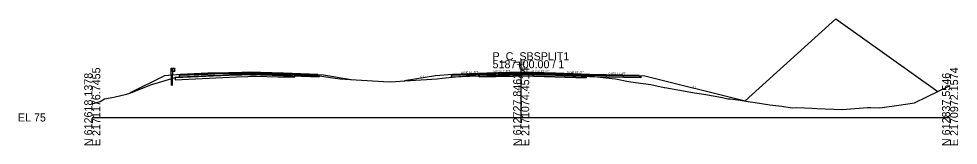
# Model space of a CAD drawing. Extents: x -26 to 1303, y -3010 to 12033.
# Drawn here: x -25.7 to 302.8, y 7990.3 to 8034.5 of the extents above; entities that cross this region are included whole.
import ezdxf

# ---------------------------------------------------------------- set-up
doc = ezdxf.new("R2010")
doc.units = 0
for name, color, linetype in [('RD_GPK_XS_Cell', 7, 'Continuous'), ('RD_PD_Final_TrvlWay', 7, 'Continuous'), ('RD_Sketch10', 7, 'Continuous'), ('RD_XS_Base', 7, 'Continuous'), ('RD_XS_ExGround', 7, 'Continuous'), ('RD_XS_ExPaveRet', 7, 'Continuous'), ('RD_XS_GR', 7, 'Continuous'), ('RD_XS_Greenside', 7, 'Continuous'), ('RD_XS_Pave', 7, 'Continuous'), ('RD_XS_PaveOvlay_CP', 7, 'Continuous'), ('RD_XS_TieSlope', 7, 'Continuous'), ('RD_XS_TX_Elev_EX', 7, 'Continuous'), ('RD_XS_TX_Elev_PR', 7, 'Continuous'), ('RD_XS_TX_Slope', 7, 'Continuous')]:
    doc.layers.add(name, color=color, linetype=linetype)

msp = doc.modelspace()

# ---------------------------------------------------------------- linework, layer by layer
at = {"layer": 'RD_GPK_XS_Cell'}
for p, q in [((150, 8000), (150, 8020)), ((0, 8000), (150, 8000)), ((150, 8000), (300, 8000))]:
    msp.add_line(p, q, dxfattribs=at)
at = {"layer": 'RD_PD_Final_TrvlWay'}
msp.add_lwpolyline([(28.05, 8011.23), (28.05, 8014.83), (27.55, 8014.79), (27.55, 8011.23)], dxfattribs=at)
at = {"layer": 'RD_Sketch10'}
msp.add_lwpolyline([(228.37, 8005.78), (260.08, 8034.49), (295.68, 8009.06)], dxfattribs=at)
at = {"layer": 'RD_XS_Base'}
for p, q in [((30.78, 8014.74), (30.38, 8014.72)), ((30.38, 8014.72), (30.38, 8014.62)), ((30.38, 8014.62), (30.38, 8014.22)), ((30.38, 8014.22), (30.78, 8014.24)), ((30.88, 8014.74), (30.78, 8014.74)), ((30.78, 8014.24), (30.88, 8014.24)), ((40.4, 8015.12), (30.88, 8014.74)), ((30.88, 8014.24), (40.4, 8014.62)), ((42.88, 8015.22), (40.4, 8015.12)), ((40.4, 8014.62), (42.88, 8014.72)), ((52.33, 8015.41), (42.88, 8015.22)), ((42.88, 8014.72), (52.33, 8014.91)), ((54.88, 8015.46), (52.33, 8015.41)), ((52.33, 8014.91), (54.88, 8014.96)), ((54.88, 8015.59), (54.88, 8015.62)), ((54.88, 8015.62), (54.88, 8015.48)), ((54.88, 8015.46), (54.88, 8015.62)), ((54.88, 8015.62), (54.88, 8015.62)), ((54.88, 8015.62), (54.88, 8015.62)), ((54.88, 8015.62), (54.88, 8014.96)), ((54.88, 8015.46), (54.88, 8015.59)), ((54.88, 8015.48), (54.88, 8014.96)), ((54.88, 8015.36), (54.88, 8015.46)), ((54.88, 8014.96), (54.88, 8015.46)), ((54.88, 8015.46), (54.88, 8015.46)), ((54.88, 8015.46), (54.88, 8015.46)), ((54.88, 8015.46), (54.88, 8015.46)), ((66.88, 8015.22), (54.88, 8015.46)), ((54.88, 8014.96), (54.88, 8015.36)), ((54.88, 8014.96), (54.88, 8014.96)), ((54.88, 8014.96), (54.88, 8014.96)), ((54.88, 8014.96), (66.88, 8014.72)), ((78.88, 8014.74), (66.88, 8015.22)), ((66.88, 8014.72), (79.38, 8014.22)), ((68.88, 8015.14), (68.88, 8015.14)), ((68.88, 8014.64), (68.88, 8014.64)), ((79.38, 8014.72), (78.88, 8014.74)), ((78.88, 8014.74), (78.88, 8014.74)), ((79.38, 8014.22), (79.38, 8014.72)), ((79.38, 8014.72), (79.38, 8014.72)), ((126, 8014.74), (125.5, 8014.72)), ((125.5, 8014.72), (125.5, 8014.72)), ((125.5, 8014.72), (125.5, 8014.22)), ((125.5, 8014.22), (126, 8014.24)), ((138, 8015.22), (126, 8014.74)), ((126, 8014.74), (126, 8014.74)), ((126, 8014.24), (138, 8014.72)), ((126, 8014.24), (126, 8014.24)), ((136, 8015.14), (136, 8015.14)), ((136, 8014.64), (136, 8014.64)), ((150, 8015.46), (138, 8015.22)), ((138, 8014.72), (150, 8014.96)), ((150, 8014.96), (150, 8015.62)), ((150, 8015.62), (150, 8015.62)), ((150, 8015.62), (150, 8015.62)), ((150, 8015.62), (150, 8015.46)), ((150, 8015.46), (150, 8015.46)), ((150, 8015.46), (162, 8015.22)), ((150, 8015.46), (150, 8015.46)), ((150, 8014.96), (150, 8015.46)), ((150, 8015.46), (150, 8015.46)), ((150, 8015.46), (150, 8015.46)), ((162, 8014.72), (150, 8014.96)), ((150, 8014.96), (150, 8014.96)), ((150, 8014.96), (150, 8014.96)), ((162, 8015.22), (162, 8015.22)), ((162, 8015.22), (174, 8014.74)), ((174, 8014.24), (162, 8014.72)), ((162, 8014.72), (162, 8014.72)), ((174, 8014.74), (174, 8014.74)), ((174, 8014.74), (191.3, 8014.39)), ((191.8, 8013.88), (174, 8014.24)), ((174, 8014.24), (174, 8014.24)), ((191.3, 8014.39), (191.3, 8014.39)), ((191.3, 8014.39), (191.8, 8014.38)), ((191.8, 8014.38), (191.8, 8014.38)), ((191.8, 8014.38), (191.8, 8013.88))]:
    msp.add_line(p, q, dxfattribs=at)
at = {"layer": 'RD_XS_ExGround'}
msp.add_lwpolyline([(0, 8004.82), (2.39, 8005.42), (2.74, 8005.56), (4.29, 8006.5), (7.59, 8007.12), (11.93, 8008.2), (13.11, 8008.48), (13.51, 8008.57), (14.62, 8009.07), (20.67, 8011.5), (21.98, 8011.83), (28.94, 8013.93), (50.49, 8014.93), (55.37, 8015.16), (57.3, 8015.13), (70.85, 8014.9), (72.05, 8014.84), (73.11, 8014.78), (79.51, 8014.5), (84.1, 8013.87), (86.66, 8013.5), (88.42, 8013.34), (101.9, 8012.56), (104.47, 8012.51), (109.36, 8012.78), (120.59, 8013.51), (122.37, 8013.69), (135.27, 8014.96), (147.05, 8015.2), (150.55, 8015.29), (154.46, 8015.16), (172.71, 8014.62), (179.55, 8013.88), (182.98, 8013.5), (187.48, 8012.58), (188.34, 8012.42), (189.99, 8012.17), (195.34, 8011.55), (199.99, 8010.52), (200.07, 8010.5), (200.1, 8010.5), (200.24, 8010.47), (210.66, 8008.56), (213.87, 8008.09), (220.38, 8007.02), (222.32, 8006.57), (223.13, 8006.54), (226.58, 8006.07), (230.1, 8005.5), (231.82, 8005.26), (236.99, 8004.46), (241.1, 8003.94), (244.81, 8003.41), (246.45, 8003.48), (251.79, 8003.3), (253.4, 8003.19), (262.22, 8002.76), (271.17, 8003.46), (271.83, 8003.5), (272.23, 8003.5), (275.37, 8003.38), (276.25, 8003.48), (282.08, 8004.28), (287.59, 8005.1), (291.84, 8007.17), (299.53, 8010.94), (300, 8011.14)], dxfattribs=at)
at = {"layer": 'RD_XS_ExPaveRet'}
for points in [[(70.85, 8014.9), (70.85, 8014.9), (70.85, 8014.9), (70.85, 8014.9), (70.85, 8014.9), (64.9, 8015), (57.3, 8015.13), (55.78, 8015.15), (55.37, 8015.16), (54.35, 8015.11), (50.49, 8014.93), (38.47, 8014.37), (28.94, 8013.93), (28.94, 8013.57), (28.94, 8013.18), (38.47, 8013.62), (50.49, 8014.18), (54.35, 8014.36), (55.37, 8014.41), (55.78, 8014.4), (57.3, 8014.38), (64.9, 8014.25), (70.85, 8014.15), (70.85, 8014.15), (70.85, 8014.15), (70.85, 8014.15), (70.85, 8014.15), (70.85, 8014.15), (70.85, 8014.54), (70.85, 8014.9), (70.85, 8014.9)], [(70.85, 8014.9), (70.85, 8014.9), (70.85, 8014.9), (70.85, 8014.9), (64.9, 8015), (57.3, 8015.13), (55.78, 8015.15), (55.37, 8015.16), (54.35, 8015.11), (50.49, 8014.93), (38.47, 8014.37), (28.94, 8013.93), (28.94, 8013.57), (28.94, 8013.18), (38.47, 8013.62), (50.49, 8014.18), (54.35, 8014.36), (55.37, 8014.41), (55.78, 8014.4), (57.3, 8014.38), (64.9, 8014.25), (70.85, 8014.15), (70.85, 8014.15), (70.85, 8014.15), (70.85, 8014.15), (70.85, 8014.54), (70.85, 8014.9)], [(172.71, 8014.62), (172.71, 8014.62), (172.71, 8013.87), (172.71, 8013.87), (154.46, 8014.41), (154.46, 8014.41), (150.55, 8014.54), (150.55, 8014.54), (150.55, 8014.54), (147.05, 8014.45), (147.05, 8014.45), (135.27, 8014.21), (135.27, 8014.96), (135.27, 8014.96), (147.05, 8015.2), (147.05, 8015.2), (150.55, 8015.29), (150.55, 8015.29), (150.55, 8015.29), (154.46, 8015.16), (154.46, 8015.16), (172.71, 8014.62), (172.71, 8014.62)], [(172.71, 8014.62), (154.46, 8015.16), (150.55, 8015.29), (147.05, 8015.2), (135.27, 8014.96), (135.27, 8014.21), (147.05, 8014.45), (150.55, 8014.54), (154.46, 8014.41), (172.71, 8013.87), (172.71, 8013.87), (172.71, 8014.62), (172.71, 8014.62)]]:
    msp.add_lwpolyline(points, dxfattribs=at)
at = {"layer": 'RD_XS_GR'}
for p, q in [((27.55, 8014.79), (27.55, 8017.23)), ((27.55, 8017.23), (27.8, 8017.23)), ((27.8, 8017.23), (28.05, 8017.23)), ((28.05, 8017.23), (28.05, 8014.83)), ((28.05, 8016.06), (28.05, 8017.23)), ((28.05, 8017.23), (28.71, 8017.23)), ((28.71, 8017.23), (28.71, 8016.06)), ((28.77, 8017.17), (28.71, 8017.23)), ((28.71, 8017.23), (28.71, 8016.99)), ((28.71, 8016.99), (28.71, 8016.06)), ((28.71, 8016.65), (28.93, 8016.88)), ((28.77, 8016.59), (28.71, 8016.65)), ((28.71, 8016.06), (28.93, 8016.29)), ((28.98, 8016.94), (28.77, 8017.17)), ((28.98, 8016.35), (28.77, 8016.59)), ((28.93, 8016.88), (28.98, 8016.94)), ((28.93, 8016.29), (28.98, 8016.35)), ((28.05, 8014.83), (27.55, 8014.79)), ((28.71, 8016.06), (28.05, 8016.06))]:
    msp.add_line(p, q, dxfattribs=at)
at = {"layer": 'RD_XS_Greenside'}
for p, q in [((25.23, 8014.61), (12.98, 8008.48)), ((80.88, 8014.9), (91.24, 8013.17)), ((120, 8014.58), (109.18, 8012.77)), ((193.3, 8014.55), (228.37, 8005.78))]:
    msp.add_line(p, q, dxfattribs=at)
at = {"layer": 'RD_XS_Pave'}
for p, q in [((40.4, 8015.44), (30.88, 8015.06)), ((40.4, 8015.28), (30.88, 8014.9)), ((30.88, 8014.9), (40.4, 8015.28)), ((30.88, 8014.74), (40.4, 8015.12)), ((30.88, 8015.06), (30.88, 8015.03)), ((30.88, 8015.03), (30.88, 8014.9)), ((30.88, 8014.9), (30.88, 8014.87)), ((30.88, 8014.87), (30.88, 8014.74)), ((42.88, 8015.54), (40.4, 8015.44)), ((42.88, 8015.38), (40.4, 8015.28)), ((40.4, 8015.28), (42.88, 8015.38)), ((40.4, 8015.12), (42.88, 8015.22)), ((52.33, 8015.73), (42.88, 8015.54)), ((52.33, 8015.57), (42.88, 8015.38)), ((42.88, 8015.38), (52.33, 8015.57)), ((42.88, 8015.22), (52.33, 8015.41)), ((54.88, 8015.78), (52.33, 8015.73)), ((54.88, 8015.62), (52.33, 8015.57)), ((52.33, 8015.57), (54.88, 8015.62)), ((52.33, 8015.41), (54.88, 8015.46)), ((66.88, 8015.54), (54.88, 8015.78)), ((54.88, 8015.78), (54.88, 8015.78)), ((54.88, 8015.78), (54.88, 8015.78)), ((54.88, 8015.59), (54.88, 8015.62)), ((54.88, 8015.62), (54.88, 8015.59)), ((54.88, 8015.46), (54.88, 8015.62)), ((54.88, 8015.62), (54.88, 8015.62)), ((54.88, 8015.62), (54.88, 8015.62)), ((54.88, 8015.62), (54.88, 8015.62)), ((54.88, 8015.62), (54.88, 8015.62)), ((54.88, 8015.62), (66.88, 8015.38)), ((66.88, 8015.38), (54.88, 8015.62)), ((54.88, 8015.62), (54.88, 8015.62)), ((54.88, 8015.62), (54.88, 8015.62)), ((54.88, 8015.62), (54.88, 8015.46)), ((54.88, 8015.46), (54.88, 8015.59)), ((54.88, 8015.59), (54.88, 8015.46)), ((54.88, 8015.46), (54.88, 8015.46)), ((54.88, 8015.46), (54.88, 8015.46)), ((54.88, 8015.46), (66.88, 8015.22)), ((78.88, 8015.06), (66.88, 8015.54)), ((66.88, 8015.38), (78.88, 8014.9)), ((78.88, 8014.9), (66.88, 8015.38)), ((66.88, 8015.22), (78.88, 8014.74)), ((68.88, 8015.46), (68.88, 8015.46)), ((68.88, 8015.3), (68.88, 8015.3)), ((68.88, 8015.3), (68.88, 8015.3)), ((68.88, 8015.14), (68.88, 8015.14)), ((78.88, 8014.9), (78.88, 8015.06)), ((78.88, 8015.06), (78.88, 8015.06)), ((78.88, 8014.74), (78.88, 8014.9)), ((78.88, 8014.9), (78.88, 8014.9)), ((138, 8015.54), (126, 8015.06)), ((138, 8015.38), (126, 8014.9)), ((126, 8014.9), (138, 8015.38)), ((126, 8014.74), (138, 8015.22)), ((126, 8015.06), (126, 8015.06)), ((126, 8015.06), (126, 8014.9)), ((126, 8014.9), (126, 8014.9)), ((126, 8014.9), (126, 8014.74)), ((136, 8015.46), (136, 8015.46)), ((136, 8015.3), (136, 8015.3)), ((136, 8015.3), (136, 8015.3)), ((136, 8015.14), (136, 8015.14)), ((150, 8015.78), (138, 8015.54)), ((150, 8015.62), (138, 8015.38)), ((138, 8015.38), (150, 8015.62)), ((138, 8015.22), (150, 8015.46)), ((162, 8015.54), (150, 8015.78)), ((150, 8015.78), (150, 8015.78)), ((150, 8015.78), (150, 8015.78)), ((150, 8015.46), (150, 8015.62)), ((150, 8015.62), (150, 8015.62)), ((150, 8015.62), (150, 8015.62)), ((150, 8015.62), (150, 8015.62)), ((150, 8015.62), (150, 8015.62)), ((150, 8015.62), (162, 8015.38)), ((162, 8015.38), (150, 8015.62)), ((150, 8015.62), (150, 8015.62)), ((150, 8015.62), (150, 8015.62)), ((150, 8015.62), (150, 8015.62)), ((150, 8015.62), (150, 8015.46)), ((150, 8015.46), (150, 8015.46)), ((150, 8015.46), (150, 8015.46)), ((150, 8015.46), (150, 8015.46)), ((150, 8015.46), (162, 8015.22)), ((174, 8015.06), (162, 8015.54)), ((162, 8015.54), (162, 8015.54)), ((162, 8015.38), (162, 8015.38)), ((162, 8015.38), (174, 8014.9)), ((174, 8014.9), (162, 8015.38)), ((162, 8015.38), (162, 8015.38)), ((162, 8015.22), (162, 8015.22)), ((162, 8015.22), (174, 8014.74)), ((191.3, 8014.71), (174, 8015.06)), ((174, 8015.06), (174, 8015.06)), ((174, 8014.9), (174, 8014.9)), ((174, 8014.9), (191.3, 8014.55)), ((191.3, 8014.55), (174, 8014.9)), ((174, 8014.9), (174, 8014.9)), ((174, 8014.74), (191.3, 8014.39)), ((174, 8014.74), (174, 8014.74)), ((191.3, 8014.55), (191.3, 8014.71)), ((191.3, 8014.71), (191.3, 8014.71)), ((191.3, 8014.39), (191.3, 8014.55)), ((191.3, 8014.55), (191.3, 8014.55))]:
    msp.add_line(p, q, dxfattribs=at)
at = {"layer": 'RD_XS_PaveOvlay_CP'}
for p, q in [((30.88, 8015.06), (42.88, 8015.54)), ((42.88, 8015.54), (54.88, 8015.78)), ((54.88, 8015.78), (66.88, 8015.54)), ((66.88, 8015.54), (78.88, 8015.06)), ((138, 8015.54), (126, 8015.06)), ((136, 8015.46), (136, 8015.46)), ((150, 8015.78), (138, 8015.54)), ((162, 8015.54), (150, 8015.78)), ((150, 8015.78), (150, 8015.78)), ((150, 8015.78), (150, 8015.78)), ((174, 8015.06), (162, 8015.54)), ((162, 8015.54), (162, 8015.54)), ((191.3, 8014.71), (174, 8015.06)), ((174, 8015.06), (174, 8015.06))]:
    msp.add_line(p, q, dxfattribs=at)
at = {"layer": 'RD_XS_TieSlope'}
for p, q in [((30.88, 8015.06), (25.23, 8014.61)), ((78.88, 8015.06), (80.88, 8014.9)), ((126, 8015.06), (120, 8014.58)), ((191.3, 8014.71), (193.3, 8014.55))]:
    msp.add_line(p, q, dxfattribs=at)

# ---------------------------------------------------------------- texts
at = {"layer": 'RD_GPK_XS_Cell'}
for s, p in [('P_C_SBSPLIT1', (140, 8020)), ('5187+00.00 / 1', (140, 8017.2)), ('EL 75', (-26, 7998.6))]:
    msp.add_text(s, height=2.8, dxfattribs=at).set_placement(p)
for s, p in [('E 2171176.7455', (2.8, 7990)), ('E 2171074.4514', (152.8, 7990)), ('E 2170972.1574', (302.8, 7990)), ('N 612618.1378', (0, 7990)), ('N 612727.8462', (150, 7990)), ('N 612837.5546', (300, 7990))]:
    msp.add_text(s, height=2.8, rotation=90, dxfattribs=at).set_placement(p)
at = {"layer": 'RD_XS_TX_Elev_EX'}
msp.add_text('90.28', height=0.6, rotation=90, dxfattribs=at).set_placement((149.68, 8016.82))
at = {"layer": 'RD_XS_TX_Elev_PR'}
msp.add_text('90.78', height=1, rotation=90, dxfattribs=at).set_placement((151.29, 8016.14))
at = {"layer": 'RD_XS_TX_Slope'}
for s, rotation, p in [('0.040 FT./FT.', 2.2906, (128.93, 8015.27)), ('0.020 FT./FT.', 1.1458, (140.16, 8015.71)), ('0.020 FT./FT.', 358.8542, (153.94, 8015.8)), ('0.040 FT./FT.', 357.7094, (165.94, 8015.48)), ('6:1', 9.4623, (114.85, 8013.78)), ('0.020 FT./FT.', 358.8542, (180.59, 8015.02)), ('4:1', 345.9638, (209.79, 8010.49))]:
    msp.add_text(s, height=0.75, rotation=rotation, dxfattribs=at).set_placement(p)

doc.saveas('drawing.dxf')
